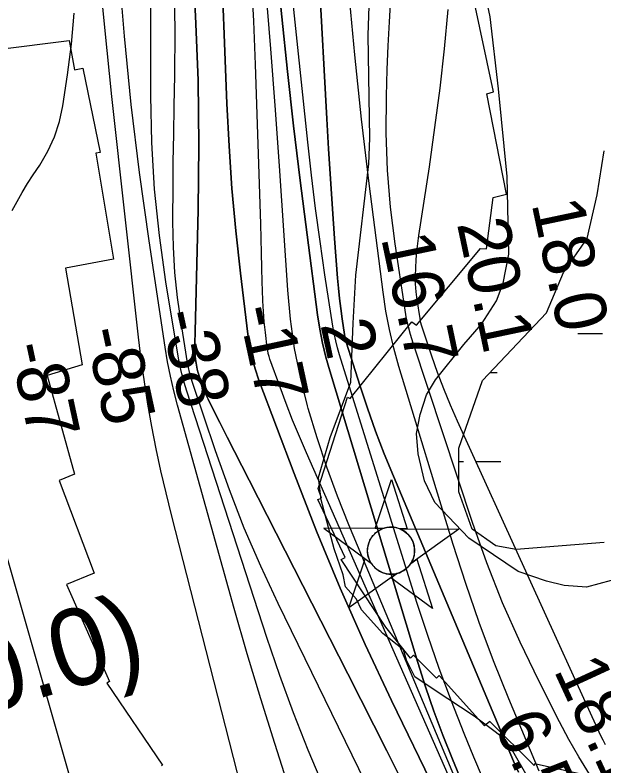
# Model space of a CAD drawing. Extents: x 3535183 to 3573198, y 534952 to 560562.
# Drawn here: x 3553490 to 3554254, y 548588 to 549561 of the extents above; entities that cross this region are included whole.
import ezdxf

# ---------------------------------------------------------------- set-up
doc = ezdxf.new("R2010")
doc.units = 0
for name, color, linetype in [('V-CHAN-NAID', 7, 'Continuous'), ('V-RIVR-EDGE', 7, 'Continuous'), ('V-RIVR-RANG', 7, 'Continuous'), ('V-RRAP-RVMT', 7, 'Continuous'), ('V-SITE-VEGE', 7, 'Continuous'), ('V-TOPO-DPTH', 7, 'Continuous'), ('V-TOPO-MAJR', 7, 'Continuous'), ('V-TOPO-MINR', 7, 'Continuous'), ('V-TOPO-WATR', 7, 'Continuous'), ('V-WETL-SWMP', 7, 'Continuous')]:
    doc.layers.add(name, color=color, linetype=linetype)

msp = doc.modelspace()

# ---------------------------------------------------------------- linework, layer by layer
at = {"layer": 'V-CHAN-NAID'}
for points in [[(3553966.85, 548895.43), (3553957.26, 548895.49), (3553978.39, 548958.98), (3553998.61, 548895.2), (3553989.02, 548895.27), (3553987.45, 548895.85), (3553985.35, 548896.47), (3553983.31, 548896.92), (3553981.27, 548897.22), (3553980.11, 548897.34), (3553978.57, 548897.42), (3553976.85, 548897.42), (3553975.48, 548897.35), (3553973.58, 548897.15), (3553972.21, 548896.93), (3553970.43, 548896.54), (3553968.9, 548896.12), (3553967.86, 548895.79)], [(3553966.85, 548895.43), (3553890.36, 548895.97), (3553951.92, 548850.57), (3553950.81, 548852.48), (3553950, 548854.1), (3553949.17, 548856.07), (3553948.48, 548858.13), (3553948.11, 548859.45), (3553947.75, 548861.08), (3553947.51, 548862.52), (3553947.32, 548864.12), (3553947.21, 548865.85), (3553947.2, 548867.44), (3553947.31, 548869.51), (3553947.49, 548871.13), (3553947.88, 548873.33), (3553948.36, 548875.25), (3553948.96, 548877.14), (3553949.62, 548878.82), (3553950.35, 548880.41), (3553951.16, 548881.94), (3553952.22, 548883.68), (3553953.25, 548885.15), (3553954.25, 548886.42), (3553955.25, 548887.57), (3553956.56, 548888.9), (3553957.61, 548889.87), (3553959.33, 548891.26), (3553960.54, 548892.13), (3553962.23, 548893.2), (3553963.96, 548894.15), (3553965.41, 548894.83)], [(3553989.02, 548895.27), (3554065.52, 548894.72), (3554003.31, 548850.2), (3554004.22, 548851.69), (3554005.2, 548853.54), (3554005.92, 548855.12), (3554006.66, 548857.08), (3554007.2, 548858.86), (3554007.6, 548860.5), (3554007.96, 548862.51), (3554008.15, 548864.09), (3554008.27, 548866.29), (3554008.24, 548868.35), (3554008.05, 548870.57), (3554007.79, 548872.33), (3554007.29, 548874.56), (3554006.65, 548876.7), (3554005.9, 548878.69), (3554005.26, 548880.13), (3554004.25, 548882.05), (3554003.19, 548883.77), (3554001.97, 548885.47), (3554000.71, 548887.01), (3553999.44, 548888.37), (3553997.81, 548889.91), (3553996.06, 548891.32), (3553994.38, 548892.49), (3553992.5, 548893.63), (3553991.02, 548894.39)], [(3553985.28, 548837.3), (3553923.08, 548792.78), (3553944.2, 548856.26), (3553951.92, 548850.57), (3553952.56, 548849.6), (3553953.94, 548847.74), (3553955.15, 548846.33), (3553956.62, 548844.83), (3553958.01, 548843.57), (3553959.46, 548842.42), (3553960.86, 548841.43), (3553962.54, 548840.4), (3553964.26, 548839.48), (3553966.05, 548838.67), (3553967.49, 548838.12), (3553969.12, 548837.59), (3553971.35, 548837.03), (3553972.88, 548836.74), (3553974.9, 548836.48), (3553976.44, 548836.38), (3553978.3, 548836.35), (3553979.99, 548836.43), (3553981.7, 548836.61), (3553983.6, 548836.92)], [(3554003.31, 548850.2), (3554011.11, 548855.78), (3554031.33, 548792.01), (3553977.48, 548831.72), (3553985.28, 548837.3), (3553986.95, 548837.77), (3553988.56, 548838.33), (3553990.72, 548839.25), (3553992.45, 548840.13), (3553994.32, 548841.24), (3553996.06, 548842.46), (3553997.61, 548843.7), (3553998.9, 548844.87), (3554000.28, 548846.29), (3554001.48, 548847.69), (3554002.6, 548849.16)]]:
    msp.add_lwpolyline(points, close=True, dxfattribs=at)
msp.add_circle((3553977.73, 548866.89), 30.54, dxfattribs=at)
at = {"layer": 'V-RIVR-EDGE'}
msp.add_lwpolyline([(3554152.17, 548577.53), (3554135.7, 548606.98), (3554125.93, 548621.71), (3554112.48, 548632.16), (3554085.57, 548652.44), (3554033.57, 548686.27), (3554008.49, 548703.49), (3553997.51, 548724.96), (3553993.87, 548738.45), (3553966.96, 548759.35), (3553939.47, 548790.06), (3553932.76, 548804.17), (3553918.71, 548820.13), (3553915.68, 548835.46), (3553904.12, 548869.19), (3553887.12, 548932.95), (3553883.52, 548961.76), (3553898.97, 549013.8), (3553925.49, 549085.43), (3553928.74, 549162.01), (3553931.96, 549223.89), (3553948.86, 549368.45), (3553950.17, 549401.53), (3553948.05, 549535.11), (3553954, 549710.34)], dxfattribs=at)
at = {"layer": 'V-RRAP-RVMT'}
for p, q in [((3554110.29, 549461.7), (3554084.34, 549583.53)), ((3553447.84, 549514.23), (3553560.33, 549528.16)), ((3553560.33, 549528.16), (3553567.39, 549490.27)), ((3553567.39, 549490.27), (3553578.37, 549492.4)), ((3553578.37, 549492.4), (3553600.61, 549383.32)), ((3554101.72, 549459.43), (3554110.29, 549461.7)), ((3554127.11, 549329.18), (3554101.72, 549459.43)), ((3553600.61, 549383.32), (3553595.03, 549382.34)), ((3553595.03, 549382.34), (3553617.87, 549244.74)), ((3554101.22, 549258.32), (3554110.13, 549324.72)), ((3554110.13, 549324.72), (3554127.11, 549329.18)), ((3554010.46, 549159.14), (3554093.64, 549258.67)), ((3554093.64, 549258.67), (3554101.22, 549258.32)), ((3553617.87, 549244.74), (3553555.6, 549233.35)), ((3553555.6, 549233.35), (3553577.48, 549107.69)), ((3553924.76, 549064.21), (3554004.61, 549163.54)), ((3554004.61, 549163.54), (3554010.46, 549159.14)), ((3553577.48, 549107.69), (3553531.96, 549094.19)), ((3553531.96, 549094.19), (3553567.51, 548966.15)), ((3553883.38, 548947.51), (3553921.42, 549065.94)), ((3553921.42, 549065.94), (3553924.76, 549064.21)), ((3553567.51, 548966.15), (3553547.72, 548957.96)), ((3553547.72, 548957.96), (3553592.73, 548837.83)), ((3553887.59, 548935.02), (3553883.38, 548947.51)), ((3553882.84, 548933.06), (3553887.59, 548935.02)), ((3553918.13, 548857.99), (3553882.84, 548933.06)), ((3553913.02, 548855.47), (3553918.13, 548857.99)), ((3553970.72, 548767.79), (3553913.02, 548855.47)), ((3553592.73, 548837.83), (3553556.96, 548822.82)), ((3553556.96, 548822.82), (3553612.92, 548697.41)), ((3554002.75, 548727.47), (3553970.72, 548767.79)), ((3554006.96, 548731.24), (3554002.75, 548727.47)), ((3554036.43, 548701.78), (3554006.96, 548731.24)), ((3554040.01, 548704.92), (3554036.43, 548701.78)), ((3554098.85, 548639.8), (3554040.01, 548704.92)), ((3553612.92, 548697.41), (3553609.45, 548695.24)), ((3553609.45, 548695.24), (3553681.63, 548588.95)), ((3554105.48, 548645.33), (3554098.85, 548639.8)), ((3554163.33, 548588.27), (3554105.48, 548645.33)), ((3553681.63, 548588.95), (3553680.03, 548587.73)), ((3554163.77, 548590.34), (3554163.33, 548588.27)), ((3554308.16, 548558.62), (3554163.77, 548590.34))]:
    msp.add_line(p, q, dxfattribs=at)
at = {"layer": 'V-SITE-VEGE'}
msp.add_lwpolyline([(3554263, 548828.12), (3554231.06, 548819.52), (3554201.83, 548821.83), (3554179.23, 548827.27), (3554142.59, 548840.09), (3554078.66, 548882.9), (3554034.59, 548929.22), (3554020.93, 548957.65), (3554012.71, 548992.32), (3554010.74, 549018.82), (3554015.4, 549043.37), (3554023.56, 549069.09), (3554035.23, 549088.58), (3554071.81, 549134.2), (3554094.78, 549160.71), (3554114.23, 549190.73), (3554122.78, 549213.73), (3554130.15, 549251.53), (3554128.12, 549352.05), (3554116.71, 549465.81), (3554106.11, 549558.92), (3554100.63, 549585.8)], dxfattribs=at)
at = {"layer": 'V-TOPO-DPTH'}
for points in [[(3553815, 549767.15), (3553835.96, 549558.84), (3553843.4, 549488.18), (3553851.29, 549417.57), (3553859.82, 549347.03), (3553868.8, 549276.55), (3553882.52, 549172.6), (3553885.41, 549154.23), (3553888.88, 549135.98), (3553893.24, 549117.92), (3553898.18, 549099.99), (3554012.36, 548722.09), (3554022.47, 548690.35), (3554033.22, 548658.84), (3554044.91, 548627.67), (3554057.23, 548596.72), (3554081.69, 548537.9)], [(3554081.69, 548537.9), (3554057.23, 548596.72), (3554044.91, 548627.67), (3554033.22, 548658.84), (3554022.47, 548690.35), (3554012.36, 548722.09), (3553898.18, 549099.99), (3553893.24, 549117.92), (3553888.88, 549135.98), (3553885.41, 549154.23), (3553882.52, 549172.6), (3553868.8, 549276.55), (3553859.82, 549347.03), (3553851.29, 549417.57), (3553843.4, 549488.18), (3553835.96, 549558.84), (3553815, 549767.15)], [(3553756.73, 549659.69), (3553764.89, 549446.54), (3553767.68, 549391.42), (3553771.38, 549336.38), (3553776.43, 549281.44), (3553782.38, 549226.57), (3553791.93, 549147.64), (3553794.32, 549132.43), (3553797.43, 549117.39), (3553801.61, 549102.61), (3553806.49, 549088.01), (3553851.94, 548966.84), (3553881.11, 548892.22), (3553911.66, 548818.19), (3553944.25, 548745.04), (3553978.21, 548672.48), (3554035.59, 548554.21)], [(3554035.59, 548554.21), (3553978.21, 548672.48), (3553944.25, 548745.04), (3553911.66, 548818.19), (3553881.11, 548892.22), (3553851.94, 548966.84), (3553806.49, 549088.01), (3553801.61, 549102.61), (3553797.43, 549117.39), (3553794.32, 549132.43), (3553791.93, 549147.64), (3553782.38, 549226.57), (3553776.43, 549281.44), (3553771.38, 549336.38), (3553767.68, 549391.42), (3553764.89, 549446.54), (3553756.73, 549659.69)], [(3553719.63, 549644.03), (3553724.44, 549560.25), (3553727.64, 549476.42), (3553728.43, 549392.55), (3553727.6, 549308.63), (3553723.78, 549151.24), (3553723.67, 549145.99), (3553723.57, 549140.74), (3553723.51, 549135.49), (3553723.47, 549130.24), (3553723.47, 549129.56), (3553723.56, 549124.66), (3553723.83, 549119.77), (3553724.33, 549114.91), (3553725, 549110.05), (3553726.29, 549102.23), (3553727.19, 549098.57), (3553731.66, 549085.26), (3553734.36, 549077.78), (3553737.27, 549070.38), (3553740.5, 549063.12), (3553743.95, 549055.95), (3553755.68, 549032.88), (3553765.16, 549014.24), (3553774.64, 548995.6), (3553784.12, 548976.97), (3553793.61, 548958.34), (3553921.65, 548707.05), (3553938.55, 548673.79), (3553955.4, 548640.5), (3553972.18, 548607.18), (3553988.9, 548573.82)], [(3553719.63, 549644.03), (3553724.44, 549560.25), (3553727.64, 549476.42), (3553728.43, 549392.55), (3553727.6, 549308.63), (3553723.78, 549151.24), (3553723.67, 549145.99), (3553723.57, 549140.74), (3553723.51, 549135.49), (3553723.47, 549130.24), (3553723.47, 549129.56), (3553723.56, 549124.66), (3553723.83, 549119.77), (3553724.33, 549114.91), (3553725, 549110.05), (3553726.29, 549102.23), (3553727.19, 549098.57), (3553731.66, 549085.26), (3553734.36, 549077.78), (3553737.27, 549070.38), (3553740.5, 549063.12), (3553743.95, 549055.95), (3553755.68, 549032.88), (3553765.16, 549014.24), (3553774.64, 548995.6), (3553784.12, 548976.97), (3553793.61, 548958.34), (3553921.65, 548707.05), (3553938.55, 548673.79), (3553955.4, 548640.5), (3553972.18, 548607.18), (3553988.9, 548573.82)], [(3554065.96, 548543.79), (3553867.97, 548993.64), (3553858.92, 549014.79), (3553850.16, 549036.07), (3553841.84, 549057.51), (3553833.81, 549079.08), (3553820.8, 549115.12), (3553819.62, 549118.78), (3553818.61, 549122.48), (3553817.85, 549126.24), (3553817.26, 549130.05), (3553814.87, 549149.76), (3553813.42, 549163.47), (3553812.25, 549177.19), (3553811.48, 549190.95), (3553810.99, 549204.72), (3553810.78, 549214.94), (3553810.35, 549233.83), (3553809.89, 549252.72), (3553809.36, 549271.61), (3553808.79, 549290.5), (3553802.22, 549497.19), (3553799.91, 549553.24), (3553796.89, 549609.24)], [(3554065.96, 548543.79), (3553867.97, 548993.64), (3553858.92, 549014.79), (3553850.16, 549036.07), (3553841.84, 549057.51), (3553833.81, 549079.08), (3553820.8, 549115.12), (3553819.62, 549118.78), (3553818.61, 549122.48), (3553817.85, 549126.24), (3553817.26, 549130.05), (3553814.87, 549149.76), (3553813.42, 549163.47), (3553812.25, 549177.19), (3553811.48, 549190.95), (3553810.99, 549204.72), (3553810.78, 549214.94), (3553810.35, 549233.83), (3553809.89, 549252.72), (3553809.36, 549271.61), (3553808.79, 549290.5), (3553802.22, 549497.19), (3553799.91, 549553.24), (3553796.89, 549609.24)], [(3553884.63, 549608.57), (3553894.59, 549426.7), (3553896.83, 549387.86), (3553899.21, 549349.04), (3553901.81, 549310.23), (3553904.55, 549271.43), (3553908.3, 549220.29), (3553909.43, 549207.08), (3553910.77, 549193.9), (3553912.42, 549180.75), (3553914.28, 549167.62), (3553917.43, 549147.16), (3553917.94, 549144.3), (3553918.54, 549141.46), (3553919.26, 549138.65), (3553920.08, 549135.86), (3553937.3, 549081.45), (3553947.19, 549051.62), (3553957.64, 549021.99), (3553968.9, 548992.66), (3553980.7, 548963.54), (3554136.57, 548593.81), (3554142.75, 548579.82)], [(3553884.63, 549608.57), (3553894.59, 549426.7), (3553896.83, 549387.86), (3553899.21, 549349.04), (3553901.81, 549310.23), (3553904.55, 549271.43), (3553908.3, 549220.29), (3553909.43, 549207.08), (3553910.77, 549193.9), (3553912.42, 549180.75), (3553914.28, 549167.62), (3553917.43, 549147.16), (3553917.94, 549144.3), (3553918.54, 549141.46), (3553919.26, 549138.65), (3553920.08, 549135.86), (3553937.3, 549081.45), (3553947.19, 549051.62), (3553957.64, 549021.99), (3553968.9, 548992.66), (3553980.7, 548963.54), (3554136.57, 548593.81), (3554142.75, 548579.82)], [(3554234.76, 548577.32), (3554221.08, 548599.46), (3554208.26, 548622.1), (3554196, 548645.08), (3554169.02, 548698.12), (3554144.87, 548748.37), (3554122.27, 548799.26), (3554102, 548851.11), (3554083.28, 548903.62), (3554006.27, 549136.14), (3554002.87, 549147.35), (3553999.86, 549158.66), (3553997.44, 549170.1), (3553995.4, 549181.64), (3553982.95, 549264.66), (3553977.1, 549312.38), (3553972.97, 549360.21), (3553971.43, 549408.19), (3553971.61, 549456.28), (3553972.67, 549490.66), (3553973.89, 549521.61), (3553975.47, 549552.54), (3553977.59, 549583.44)]]:
    msp.add_lwpolyline(points, dxfattribs=at)
at = {"layer": 'V-TOPO-MAJR'}
msp.add_lwpolyline([(3553944.55, 548566.24), (3553831.28, 548798.35), (3553808.73, 548846.94), (3553787.48, 548896.06), (3553768.18, 548945.98), (3553750.16, 548996.43), (3553720.1, 549086.15), (3553718.24, 549092.18), (3553716.58, 549098.25), (3553715.22, 549104.39), (3553714.05, 549110.59), (3553705.48, 549162.83), (3553700.99, 549195.24), (3553697.57, 549227.75), (3553695.76, 549260.38), (3553695.02, 549293.1), (3553695.03, 549299.36), (3553695.21, 549335.28), (3553695.52, 549371.19), (3553696.03, 549407.1), (3553696.67, 549443.01), (3553697.51, 549483.55), (3553697.88, 549539.71), (3553697.22, 549595.84)], dxfattribs=at)
at = {"layer": 'V-TOPO-MINR'}
for points in [[(3554081.69, 548537.9), (3554057.23, 548596.72), (3554044.91, 548627.67), (3554033.22, 548658.84), (3554022.47, 548690.35), (3554012.36, 548722.09), (3553898.18, 549099.99), (3553893.24, 549117.92), (3553888.88, 549135.98), (3553885.41, 549154.23), (3553882.52, 549172.6), (3553868.8, 549276.55), (3553859.82, 549347.03), (3553851.29, 549417.57), (3553843.4, 549488.18), (3553835.96, 549558.84), (3553815, 549767.15)], [(3554096.39, 548572.98), (3554085.02, 548599.21), (3554072.48, 548629.92), (3554055.93, 548671.97), (3554040.09, 548714.27), (3554025.33, 548756.96), (3554011.29, 548799.91), (3553910.92, 549120.68), (3553908.27, 549129.87), (3553905.91, 549139.13), (3553903.96, 549148.49), (3553902.3, 549157.91), (3553892.06, 549224.72), (3553885.79, 549267.64), (3553879.93, 549310.61), (3553874.67, 549353.66), (3553869.82, 549396.76), (3553832.25, 549753.31)], [(3554035.59, 548554.21), (3553978.21, 548672.48), (3553944.25, 548745.04), (3553911.66, 548818.19), (3553881.11, 548892.22), (3553851.94, 548966.84), (3553806.49, 549088.01), (3553801.61, 549102.61), (3553797.43, 549117.39), (3553794.32, 549132.43), (3553791.93, 549147.64), (3553782.38, 549226.57), (3553776.43, 549281.44), (3553771.38, 549336.38), (3553767.68, 549391.42), (3553764.89, 549446.54), (3553756.73, 549659.69)], [(3553988.9, 548573.82), (3553972.18, 548607.18), (3553955.4, 548640.5), (3553938.55, 548673.79), (3553921.65, 548707.05), (3553793.61, 548958.34), (3553784.12, 548976.97), (3553774.64, 548995.6), (3553765.16, 549014.24), (3553755.68, 549032.88), (3553743.95, 549055.95), (3553740.5, 549063.12), (3553737.27, 549070.38), (3553734.36, 549077.78), (3553731.66, 549085.26), (3553727.19, 549098.57), (3553726.29, 549102.23), (3553725, 549110.05), (3553724.33, 549114.91), (3553723.83, 549119.77), (3553723.56, 549124.66), (3553723.47, 549129.56), (3553723.47, 549130.24), (3553723.51, 549135.49), (3553723.57, 549140.74), (3553723.67, 549145.99), (3553723.78, 549151.24), (3553727.6, 549308.63), (3553728.43, 549392.55), (3553727.64, 549476.42), (3553724.44, 549560.25), (3553719.63, 549644.03)], [(3553845.67, 548558.69), (3553826.91, 548616.68), (3553808.71, 548674.83), (3553791.35, 548733.25), (3553774.56, 548791.83), (3553701.06, 549055.53), (3553696.22, 549074.19), (3553691.84, 549092.95), (3553688.14, 549111.86), (3553684.91, 549130.87), (3553664, 549268.83), (3553651.72, 549357.01), (3553640.88, 549445.35), (3553632.17, 549533.92), (3553624.9, 549622.65)], [(3554065.96, 548543.79), (3553867.97, 548993.64), (3553858.92, 549014.79), (3553850.16, 549036.07), (3553841.84, 549057.51), (3553833.81, 549079.08), (3553820.8, 549115.12), (3553819.62, 549118.78), (3553818.61, 549122.48), (3553817.85, 549126.24), (3553817.26, 549130.05), (3553814.87, 549149.76), (3553813.42, 549163.47), (3553812.25, 549177.19), (3553811.48, 549190.95), (3553810.99, 549204.72), (3553810.78, 549214.94), (3553810.35, 549233.83), (3553809.89, 549252.72), (3553809.36, 549271.61), (3553808.79, 549290.5), (3553802.22, 549497.19), (3553799.91, 549553.24), (3553796.89, 549609.24)], [(3554073.94, 548540.89), (3553923.01, 548900.33), (3553908.21, 548937.51), (3553894.35, 548975.01), (3553881.9, 549013.01), (3553870.39, 549051.34), (3553869.43, 549054.77), (3553860.28, 549091.83), (3553852.7, 549129.15), (3553847.45, 549166.88), (3553843.77, 549204.87), (3553833.63, 549359.27), (3553828.07, 549438.52), (3553822.02, 549517.74), (3553815.26, 549596.9)], [(3554169.52, 548581.08), (3554130.38, 548674.68), (3554110.56, 548724.14), (3554091.75, 548773.97), (3554074.46, 548824.34), (3554058.19, 548875.08), (3553987.97, 549105.86), (3553981.4, 549129.58), (3553975.65, 549153.47), (3553971.11, 549177.63), (3553967.38, 549201.96), (3553949.4, 549342.96), (3553939.51, 549426.32), (3553930.56, 549509.78), (3553923.06, 549593.38)], [(3553890.47, 548560.39), (3553870.44, 548608.26), (3553851.33, 548656.48), (3553833.62, 548705.22), (3553816.84, 548754.32), (3553712.82, 549073.67), (3553709.47, 549084.84), (3553706.45, 549096.1), (3553703.96, 549107.48), (3553701.81, 549118.95), (3553685.96, 549215.61), (3553677.62, 549275.59), (3553671.22, 549335.74), (3553667.76, 549396.12), (3553666.25, 549456.66), (3553666.18, 549553.61), (3553666.23, 549580.56)], [(3554234.76, 548577.32), (3554221.08, 548599.46), (3554208.26, 548622.1), (3554196, 548645.08), (3554169.02, 548698.12), (3554144.87, 548748.37), (3554122.27, 548799.26), (3554102, 548851.11), (3554083.28, 548903.62), (3554006.27, 549136.14), (3554002.87, 549147.35), (3553999.86, 549158.66), (3553997.44, 549170.1), (3553995.4, 549181.64), (3553982.95, 549264.66), (3553977.1, 549312.38), (3553972.97, 549360.21), (3553971.43, 549408.19), (3553971.61, 549456.28), (3553972.67, 549490.66), (3553973.89, 549521.61), (3553975.47, 549552.54), (3553977.59, 549583.44)], [(3553818.57, 548422.89), (3553693.03, 548913.25), (3553686.03, 548941.74), (3553679.42, 548970.32), (3553673.37, 548999.02), (3553667.7, 549027.81), (3553662.64, 549056.71), (3553658.01, 549085.67), (3553654.03, 549114.73), (3553650.48, 549143.85), (3553616.01, 549455.81), (3553609.67, 549515.54), (3553603.68, 549575.31)], [(3554255.55, 548615.32), (3554252.46, 548621.09), (3554249.57, 548626.98), (3554063.64, 549034.94), (3554054.58, 549055.69), (3554045.96, 549076.6), (3554037.99, 549097.78), (3554030.47, 549119.13), (3554017.95, 549156.49), (3554017.09, 549159.31), (3554016.33, 549162.15), (3554015.71, 549165.03), (3554015.2, 549167.93), (3554011.59, 549192.01), (3554010.35, 549202.41), (3554009.54, 549212.82), (3554009.36, 549223.27), (3554009.61, 549233.73), (3554010.33, 549244.2), (3554011.25, 549254.65), (3554012.47, 549265.06), (3554013.89, 549275.46), (3554027.38, 549364.63), (3554034.59, 549415.49), (3554041.16, 549466.43), (3554046.79, 549517.48), (3554051.77, 549568.61)], [(3553486.58, 549307.97), (3553492.94, 549319.81), (3553499.57, 549331.49), (3553506.61, 549342.92), (3553513.91, 549354.2), (3553522.43, 549366.87), (3553532.88, 549384.88), (3553541.64, 549403.55), (3553547.87, 549423.21), (3553552.4, 549443.53), (3553558.58, 549483.66), (3553563.52, 549523.79), (3553566.83, 549564)], [(3553614.11, 548389.7), (3553430.53, 549030.68)]]:
    msp.add_lwpolyline(points, dxfattribs=at)
at = {"layer": 'V-TOPO-WATR'}
msp.add_lwpolyline([(3554142.75, 548579.82), (3554136.57, 548593.81), (3553980.7, 548963.54), (3553968.9, 548992.66), (3553957.64, 549021.99), (3553947.19, 549051.62), (3553937.3, 549081.45), (3553920.08, 549135.86), (3553919.26, 549138.65), (3553918.54, 549141.46), (3553917.94, 549144.3), (3553917.43, 549147.16), (3553914.28, 549167.62), (3553912.42, 549180.75), (3553910.77, 549193.9), (3553909.43, 549207.08), (3553908.3, 549220.29), (3553904.55, 549271.43), (3553901.81, 549310.23), (3553899.21, 549349.04), (3553896.83, 549387.86), (3553894.59, 549426.7), (3553884.63, 549608.57)], dxfattribs=at)
at = {"layer": 'V-WETL-SWMP'}
for p, q in [((3554219.78, 549148.57), (3554251.78, 549148.57)), ((3554105.86, 549097.83), (3554115.19, 549097.83)), ((3554065.44, 548982.4), (3554071.78, 548982.4)), ((3554087.78, 548982.4), (3554119.78, 548982.4))]:
    msp.add_line(p, q, dxfattribs=at)
msp.add_lwpolyline([(3554253.72, 548877.38), (3554139.88, 548868.62), (3554113.61, 548873), (3554082.96, 548894.89), (3554065.44, 548943.06), (3554065.44, 548999.98), (3554096.09, 549087.55), (3554179.29, 549175.12), (3554201.18, 549227.67), (3554231.83, 549271.45), (3554244.97, 549328.37), (3554253.72, 549385.29)], dxfattribs=at)

# ---------------------------------------------------------------- texts
at = {"layer": 'V-CHAN-NAID'}
for s, rotation, p in [('THIRTY-FIVE MILE POINT "130" (130.0)', 16.48298, (3551329.24, 548026.44)), ('ENTERGY INTAKE -DISCHARGE (129.8)', 44.4073, (3552926.8, 546850.56))]:
    msp.add_text(s, height=100, rotation=rotation, dxfattribs=at).set_placement(p)
at = {"layer": 'V-RIVR-RANG'}
for s, rotation, p in [('18.0', 281.89833, (3554159.6, 549317.11)), ('20.1', 281.89833, (3554062.88, 549291.1)), ('16.7', 281.89833, (3553964.59, 549272.57)), ('-17', 282.17875, (3553779.31, 549180.3)), ('-38', 282.17875, (3553678.28, 549174.4)), ('2', 282.17875, (3553885.9, 549160.41)), ('-85', 282.17875, (3553580.81, 549151.99)), ('-87', 282.17875, (3553482.79, 549132.17)), ('18.1', 294.73833, (3554187.84, 548712.18)), ('6.5', 294.73833, (3554110.04, 548642.08))]:
    msp.add_text(s, height=67, rotation=rotation, dxfattribs=at).set_placement(p)

doc.saveas('drawing.dxf')
